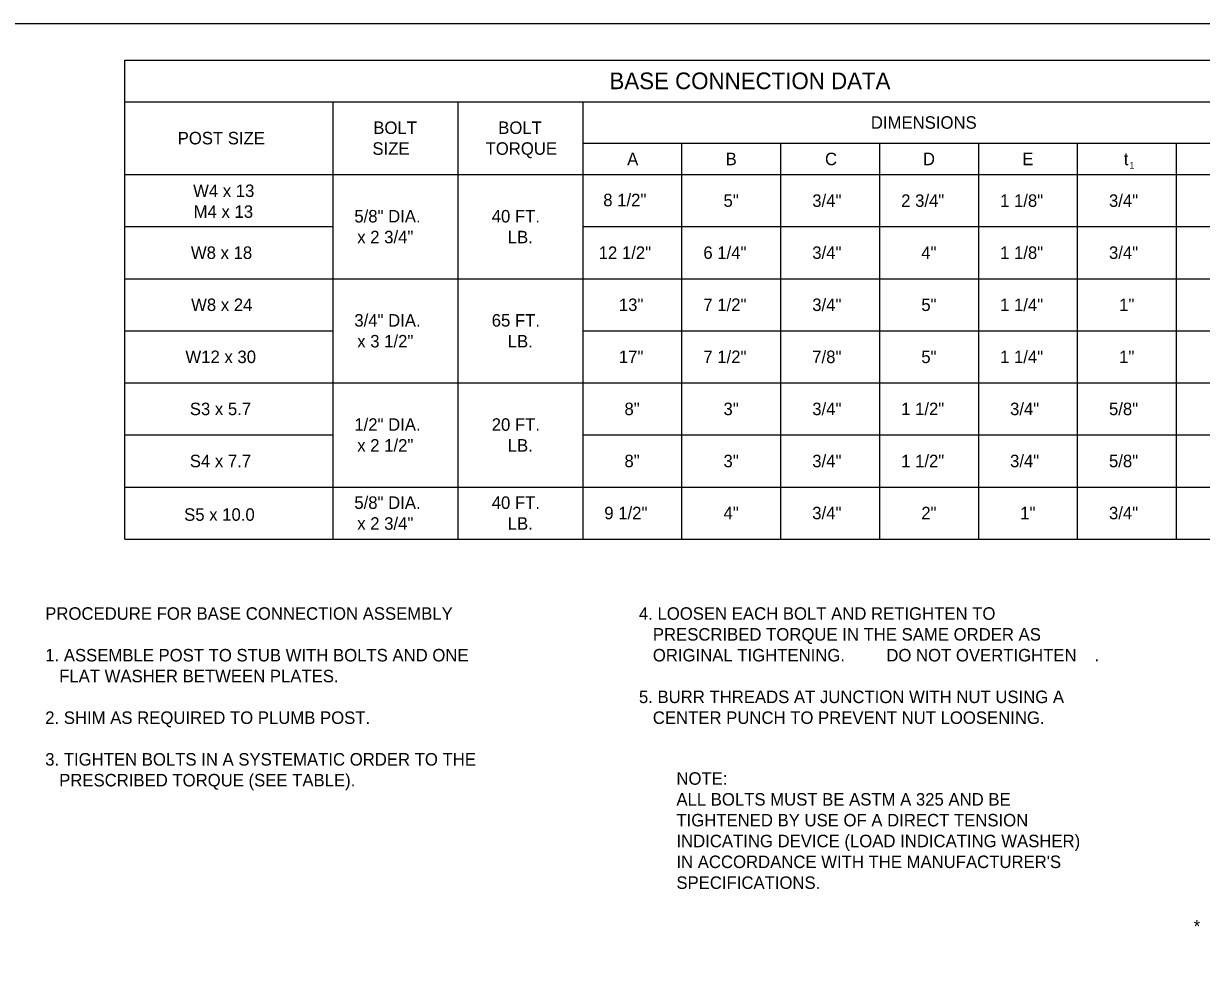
# Model space of a CAD drawing. Extents: x 49991.4 to 50021, y 49987.6 to 50011.4.
# Drawn here: x 50002.29 to 50007.94, y 49994.44 to 49999 of the extents above; entities that cross this region are included whole.
import ezdxf

# ---------------------------------------------------------------- set-up
doc = ezdxf.new("R2010")
doc.units = 0
doc.layers.add('Level 1', color=7, linetype='Continuous')
doc.layers.add('Level 2', color=7, linetype='Continuous')

msp = doc.modelspace()

# ---------------------------------------------------------------- linework, layer by layer
at = {"layer": 'Level 1'}
msp.add_lwpolyline([(49999.3835, 49998.9992), (50016.7501, 49998.9992), (50016.7501, 49987.7988), (49999.3835, 49987.7988)], close=True, dxfattribs=at)
at = {"layer": 'Level 2'}
for p, q in [((50002.7742, 49998.8242), (50016.4992, 49998.8242)), ((50002.7742, 49996.5242), (50002.7742, 49998.8242)), ((50002.7742, 49998.6242), (50016.4992, 49998.6242)), ((50003.7742, 49996.5242), (50003.7742, 49998.6242)), ((50004.3742, 49996.5242), (50004.3742, 49998.6242)), ((50004.9742, 49996.5242), (50004.9742, 49998.6242)), ((50004.9742, 49998.4242), (50008.2992, 49998.4242)), ((50005.4492, 49996.5242), (50005.4492, 49998.4242)), ((50005.9242, 49996.5242), (50005.9242, 49998.4242)), ((50006.3992, 49996.5242), (50006.3992, 49998.4242)), ((50006.8742, 49996.5242), (50006.8742, 49998.4242)), ((50007.3492, 49996.5242), (50007.3492, 49998.4242)), ((50007.8242, 49996.5242), (50007.8242, 49998.4242)), ((50002.7742, 49998.2742), (50016.4992, 49998.2742)), ((50002.7742, 49998.0242), (50003.7742, 49998.0242)), ((50004.9742, 49998.0242), (50016.4992, 49998.0242)), ((50002.7742, 49997.7742), (50016.4992, 49997.7742)), ((50002.7742, 49997.5242), (50003.7742, 49997.5242)), ((50004.9742, 49997.5242), (50016.4992, 49997.5242)), ((50002.7742, 49997.2742), (50016.4992, 49997.2742)), ((50002.7742, 49997.0242), (50003.7742, 49997.0242)), ((50004.9742, 49997.0242), (50016.4992, 49997.0242)), ((50002.7742, 49996.7742), (50016.4992, 49996.7742)), ((50002.7742, 49996.5242), (50016.4992, 49996.5242))]:
    msp.add_line(p, q, dxfattribs=at)

# ---------------------------------------------------------------- texts
for s, height, p in [('BASE CONNECTION DATA', 0.08, (50005.1011, 49998.6842)), ('DIMENSIONS', 0.06, (50006.3564, 49998.4942)), ('BOLT', 0.06, (50003.9668, 49998.4692)), ('BOLT', 0.06, (50004.5668, 49998.4692)), ('POST SIZE', 0.06, (50003.0274, 49998.4192)), ('SIZE', 0.06, (50003.9627, 49998.3692)), ('TORQUE', 0.06, (50004.5061, 49998.3692)), ('A', 0.06, (50005.186, 49998.3192)), ('B', 0.06, (50005.659, 49998.3192)), ('C', 0.06, (50006.1362, 49998.3192)), ('D', 0.06, (50006.6064, 49998.3192)), ('E', 0.06, (50007.0837, 49998.3192)), ('t', 0.06, (50007.5711, 49998.3192)), ('1', 0.0325, (50007.5978, 49998.3019)), ('W4 x 13', 0.06, (50003.1015, 49998.1665)), ('8 1/2"', 0.06, (50005.0713, 49998.1222)), ('5"', 0.06, (50005.6487, 49998.1192)), ('3/4"', 0.06, (50006.075, 49998.1192)), ('2 3/4"', 0.06, (50006.502, 49998.1192)), ('1 1/8"', 0.06, (50006.977, 49998.1192)), ('3/4"', 0.06, (50007.5, 49998.1192)), ('M4 x 13', 0.06, (50003.1042, 49998.0665)), ('5/8" DIA.', 0.06, (50003.8758, 49998.0442)), ('40 FT.', 0.06, (50004.5356, 49998.0442)), ('x 2 3/4"', 0.06, (50003.8898, 49997.9442)), ('LB.', 0.06, (50004.6125, 49997.9442)), ('W8 x 18', 0.06, (50003.0909, 49997.8692)), ('12 1/2"', 0.06, (50005.0493, 49997.8692)), ('6 1/4"', 0.06, (50005.552, 49997.8692)), ('3/4"', 0.06, (50006.075, 49997.8692)), ('4"', 0.06, (50006.5987, 49997.8692)), ('1 1/8"', 0.06, (50006.977, 49997.8692)), ('3/4"', 0.06, (50007.5, 49997.8692)), ('W8 x 24', 0.06, (50003.0919, 49997.6192)), ('13"', 0.06, (50005.1461, 49997.6192)), ('7 1/2"', 0.06, (50005.552, 49997.6192)), ('3/4"', 0.06, (50006.075, 49997.6192)), ('5"', 0.06, (50006.5987, 49997.6192)), ('1 1/4"', 0.06, (50006.977, 49997.6192)), ('1"', 0.06, (50007.5487, 49997.6192)), ('3/4" DIA.', 0.06, (50003.8758, 49997.5442)), ('65 FT.', 0.06, (50004.5356, 49997.5442)), ('x 3 1/2"', 0.06, (50003.8898, 49997.4442)), ('LB.', 0.06, (50004.6125, 49997.4442)), ('W12 x 30', 0.06, (50003.0647, 49997.3692)), ('17"', 0.06, (50005.1461, 49997.3692)), ('7 1/2"', 0.06, (50005.552, 49997.3692)), ('7/8"', 0.06, (50006.075, 49997.3692)), ('5"', 0.06, (50006.5987, 49997.3692)), ('1 1/4"', 0.06, (50006.977, 49997.3692)), ('1"', 0.06, (50007.5487, 49997.3692)), ('S3 x 5.7', 0.06, (50003.0857, 49997.1192)), ('8"', 0.06, (50005.173, 49997.1192)), ('3"', 0.06, (50005.6487, 49997.1192)), ('3/4"', 0.06, (50006.075, 49997.1192)), ('1 1/2"', 0.06, (50006.502, 49997.1192)), ('3/4"', 0.06, (50007.025, 49997.1192)), ('5/8"', 0.06, (50007.5, 49997.1192)), ('1/2" DIA.', 0.06, (50003.8758, 49997.0442)), ('20 FT.', 0.06, (50004.5356, 49997.0442)), ('x 2 1/2"', 0.06, (50003.8898, 49996.9442)), ('LB.', 0.06, (50004.6125, 49996.9442)), ('S4 x 7.7', 0.06, (50003.0857, 49996.8692)), ('8"', 0.06, (50005.173, 49996.8692)), ('3"', 0.06, (50005.6487, 49996.8692)), ('3/4"', 0.06, (50006.075, 49996.8692)), ('1 1/2"', 0.06, (50006.502, 49996.8692)), ('3/4"', 0.06, (50007.025, 49996.8692)), ('5/8"', 0.06, (50007.5, 49996.8692)), ('5/8" DIA.', 0.06, (50003.8758, 49996.6692)), ('40 FT.', 0.06, (50004.5356, 49996.6692)), ('9 1/2"', 0.06, (50005.0763, 49996.6192)), ('3/4"', 0.06, (50006.075, 49996.6192)), ('3/4"', 0.06, (50007.5, 49996.6192)), ('S5 x 10.0', 0.06, (50003.0584, 49996.612)), ('x 2 3/4"', 0.06, (50003.8898, 49996.5692)), ('LB.', 0.06, (50004.6125, 49996.5692)), ('4"', 0.06, (50005.6487, 49996.6192)), ('2"', 0.06, (50006.5987, 49996.6192)), ('1"', 0.06, (50007.0737, 49996.6192)), ('PROCEDURE FOR BASE CONNECTION ASSEMBLY', 0.06, (50002.3914, 49996.1368)), ('4. LOOSEN EACH BOLT AND RETIGHTEN TO', 0.06, (50005.2426, 49996.1368)), ('   PRESCRIBED TORQUE IN THE SAME ORDER AS', 0.06, (50005.2426, 49996.0368)), ('1. ASSEMBLE POST TO STUB WITH BOLTS AND ONE', 0.06, (50002.3914, 49995.9368)), ('   ORIGINAL TIGHTENING. ', 0.06, (50005.2426, 49995.9368)), ('DO NOT OVERTIGHTEN', 0.06, (50006.4307, 49995.9368)), ('.', 0.06, (50007.4301, 49995.9368)), ('   FLAT WASHER BETWEEN PLATES.', 0.06, (50002.3914, 49995.8368)), ('5. BURR THREADS AT JUNCTION WITH NUT USING A', 0.06, (50005.2426, 49995.7368)), ('2. SHIM AS REQUIRED TO PLUMB POST.', 0.06, (50002.3914, 49995.6368)), ('   CENTER PUNCH TO PREVENT NUT LOOSENING.', 0.06, (50005.2426, 49995.6368)), ('3. TIGHTEN BOLTS IN A SYSTEMATIC ORDER TO THE', 0.06, (50002.3914, 49995.4368)), ('   PRESCRIBED TORQUE (SEE TABLE).', 0.06, (50002.3914, 49995.3368)), ('NOTE:', 0.06, (50005.4226, 49995.3448)), ('ALL BOLTS MUST BE ASTM A 325 AND BE', 0.06, (50005.4226, 49995.2448)), ('TIGHTENED BY USE OF A DIRECT TENSION', 0.06, (50005.4226, 49995.1448)), ('INDICATING DEVICE (LOAD INDICATING WASHER)', 0.06, (50005.4226, 49995.0448)), ("IN ACCORDANCE WITH THE MANUFACTURER'S", 0.06, (50005.4226, 49994.9448)), ('SPECIFICATIONS.', 0.06, (50005.4226, 49994.8448)), ('*', 0.06, (50007.9069, 49994.6354))]:
    msp.add_text(s, height=height, dxfattribs=at).set_placement(p)

doc.saveas('drawing.dxf')
